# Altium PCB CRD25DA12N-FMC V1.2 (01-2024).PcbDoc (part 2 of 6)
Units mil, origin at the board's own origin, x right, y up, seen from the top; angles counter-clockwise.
Board outline 8000 x 8000 mil, 6 copper layers (Top Layer, Layer 2, Layer 3, Layer 4, Layer 5, Bottom Layer), stack 91 mil thick; 574 components, 325 nets, 1631 pads, 633 vias.
Unrouted connection lines stored in the file: 1.
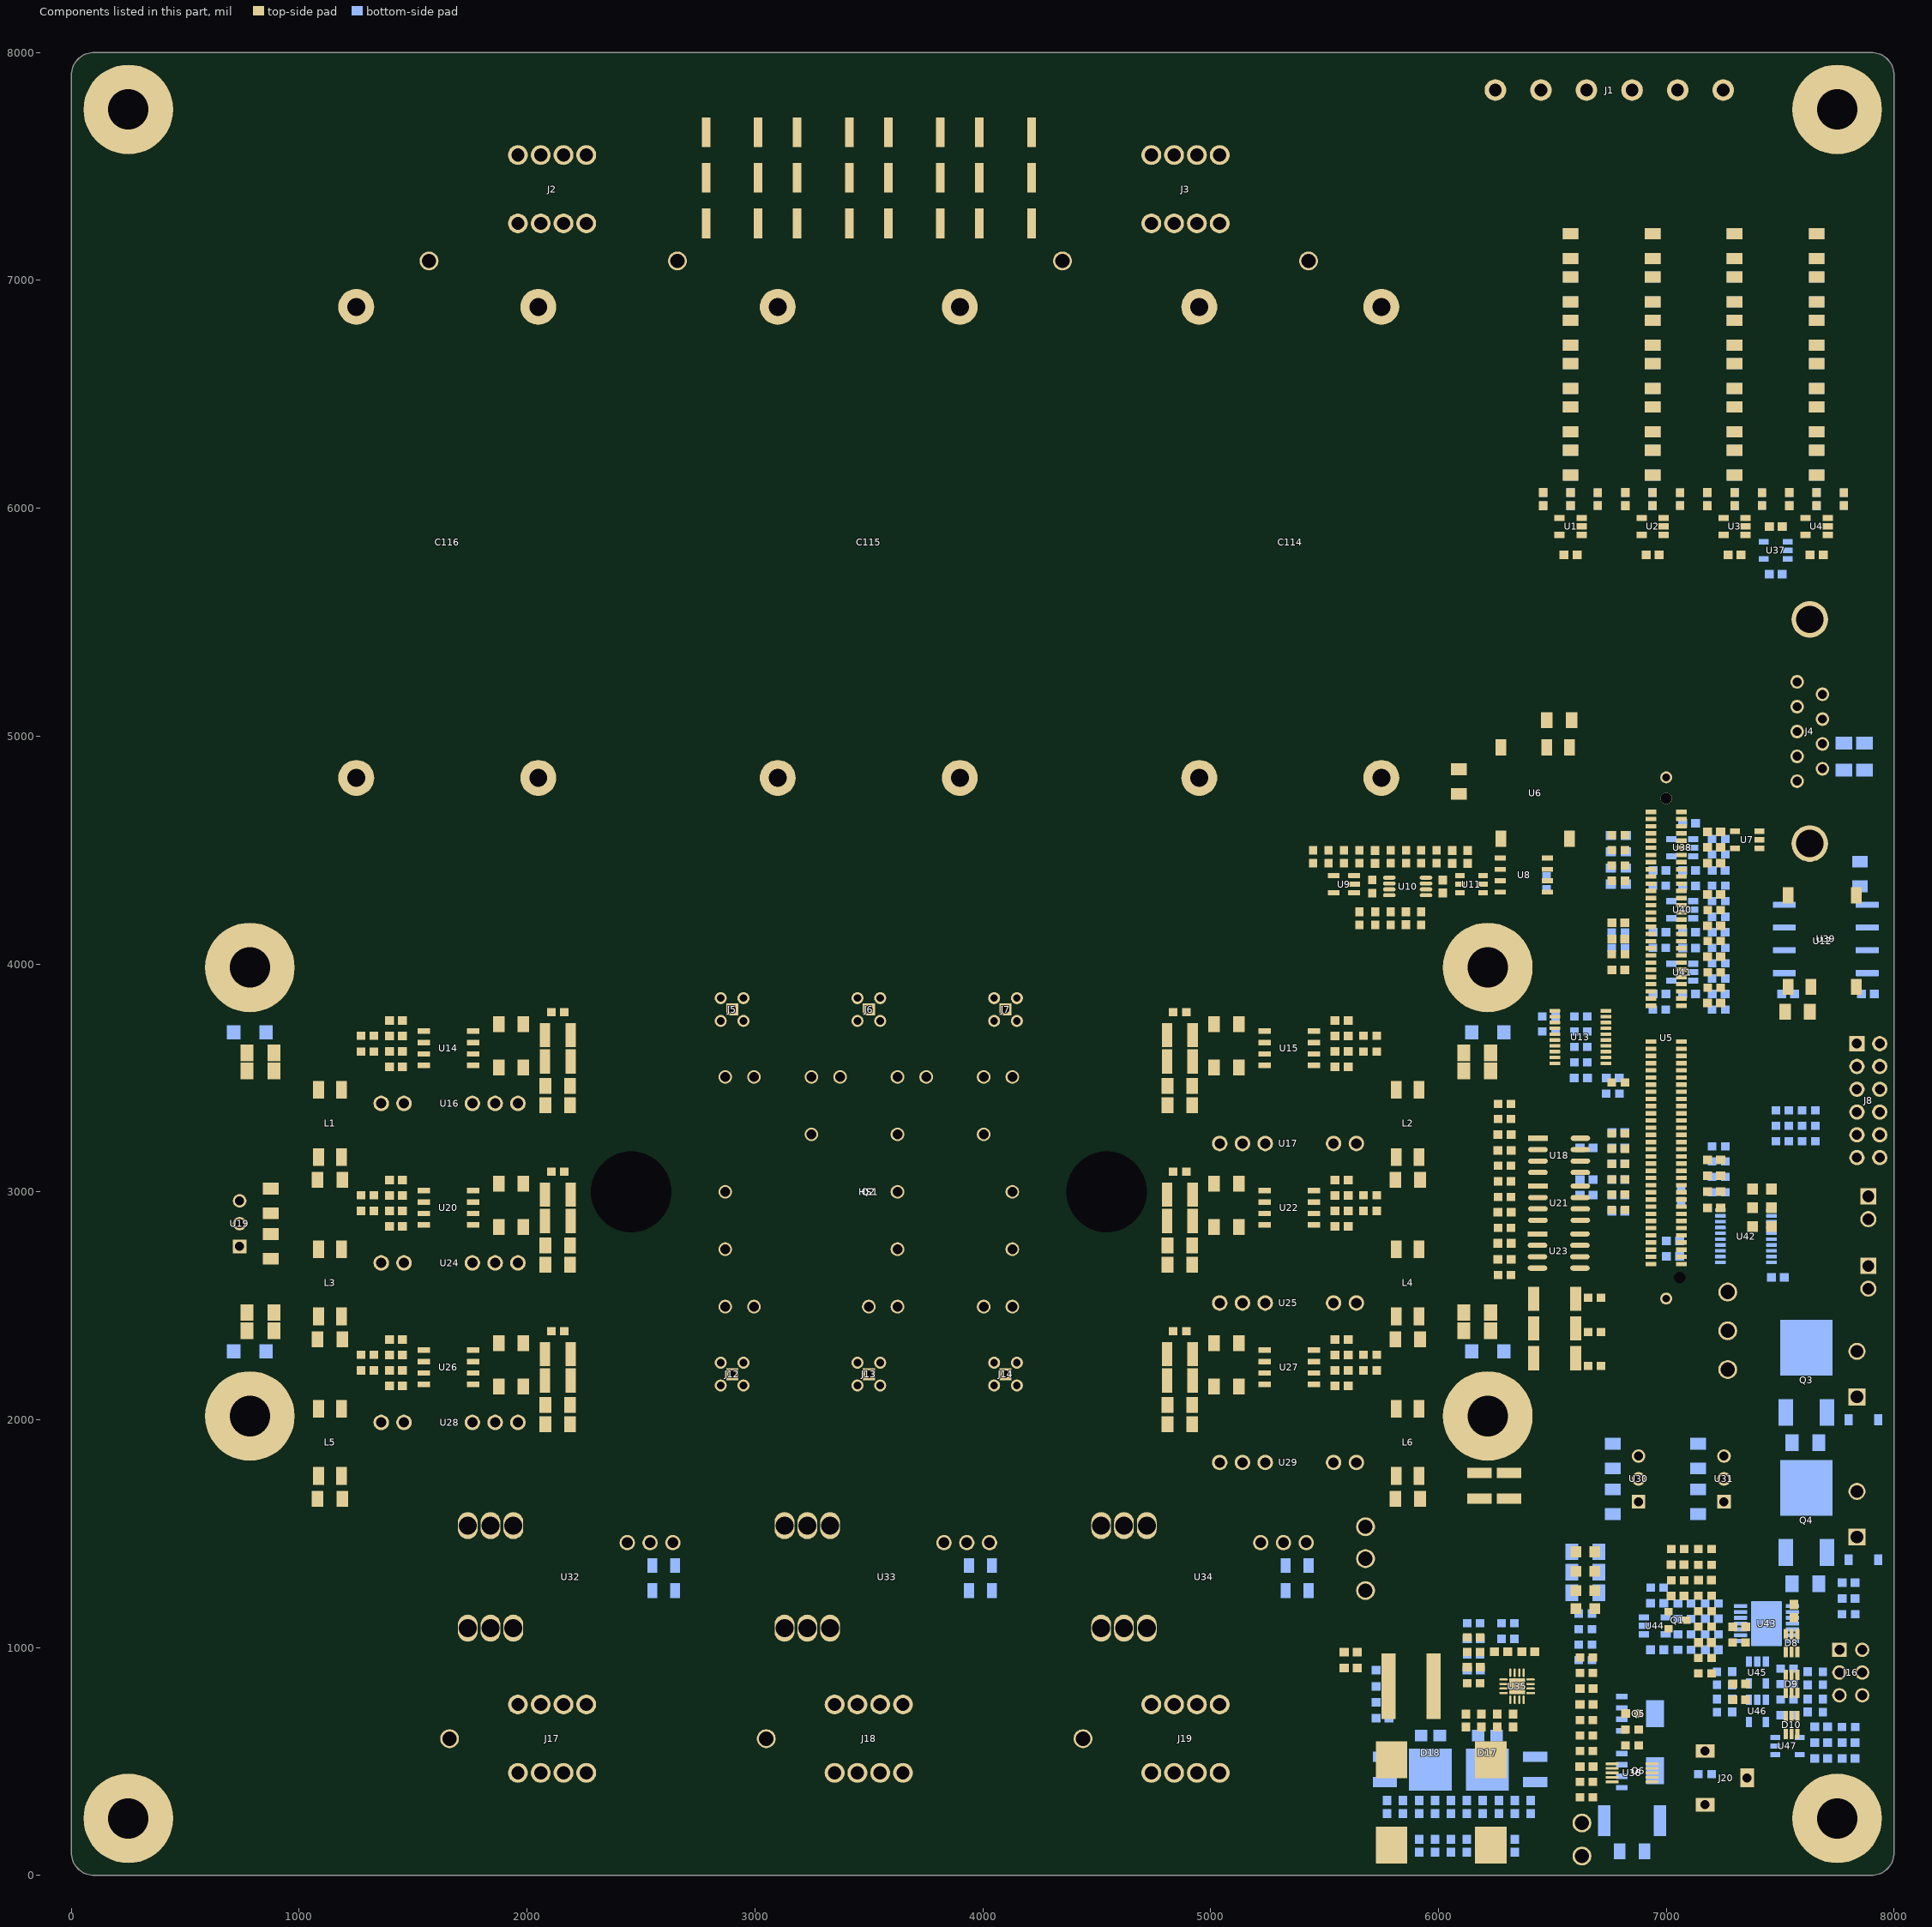
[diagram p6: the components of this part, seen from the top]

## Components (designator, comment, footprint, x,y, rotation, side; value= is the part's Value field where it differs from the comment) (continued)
R171 "TNPW1206249KBEEA" RESC3216X65X50NL15T25 6940,6200 r270 bottom value=249kΩ (schematic designator R178)
R172 "TNPW1206249KBEEA" RESC3216X65X50NL15T25 6580,6200 r270 bottom value=249kΩ (schematic designator R179)
R173 "ERJ-PB3B1801V" FP-MCR03-IPC_B 7780,6040 r90 bottom value=1.8kΩ (schematic designator R180)
R174 "RC0603FR-074K99L" FP-MCR03-IPC_B 7540,6040 r270 bottom value=4.99kΩ (schematic designator R181)
R175 "ERJ-PB3B1801V" FP-MCR03-IPC_B 7420,6040 r90 bottom value=1.8kΩ (schematic designator R182)
R176 "RC0603FR-074K99L" FP-MCR03-IPC_B 7180,6040 r270 bottom value=4.99kΩ (schematic designator R183)
R177 "ERJ-PB3B1801V" FP-MCR03-IPC_B 7060,6040 r90 bottom value=1.8kΩ (schematic designator R184)
R178 "RC0603FR-074K99L" FP-MCR03-IPC_B 6820,6040 r270 bottom value=4.99kΩ (schematic designator R185)
R179 "ERJ-PB3B3741V" FP-MCR03-IPC_B 6700,6040 r270 bottom value=3.74kΩ (schematic designator R186)
R180 "RC0603FR-074K99L" FP-MCR03-IPC_B 6460,6040 r270 bottom value=4.99kΩ (schematic designator R187)
R181 "RC1206FR-07249RL" FP-MCR18-IPC_A 7870,4910 r90 bottom value=249Ω (schematic designator R188)
R182 "RC1206FR-07249RL" FP-MCR18-IPC_A 7780,4910 r90 bottom value=249Ω (schematic designator R189)
R183 "RMCF0603FT1K33" FP-MCR03-IPC_B 7230,4548 r180 bottom value=1.33kΩ (schematic designator R190)
R184 "RMCF0603FT7K15" FP-MCR03-IPC_B 7230,4480 r180 bottom value=7.15kΩ (schematic designator R191)
R185 "ERA3AEB4021V" FP-MCR03-IPC_B 7230,4343 r0 bottom value=4.02kΩ (schematic designator R192)
R186 "RC0603FR-077K87L" FP-MCR03-IPC_B 6970,4343 r0 bottom value=7.87kΩ (schematic designator R193)
R187 "RMCF0603FT1K33" FP-MCR03-IPC_B 7230,4275 r180 bottom value=1.33kΩ (schematic designator R194)
R188 "RMCF0603FT7K15" FP-MCR03-IPC_B 7230,4207 r180 bottom value=7.15kΩ (schematic designator R195)
R189 "ERJ-3EKF49R9V" FP-MCR03-IPC_B 6790,4139 r0 bottom value=49.9Ω (schematic designator R196)
R190 "ERA3AEB4021V" FP-MCR03-IPC_B 7230,4070 r0 bottom value=4.02kΩ (schematic designator R197)
R191 "RC0603FR-077K87L" FP-MCR03-IPC_B 6970,4070 r0 bottom value=7.87kΩ (schematic designator R198)
R192 "ERJ-3EKF49R9V" FP-MCR03-IPC_B 6790,4070 r0 bottom value=49.9Ω (schematic designator R199)
R193 "RMCF0603FT1K33" FP-MCR03-IPC_B 7230,4003 r180 bottom value=1.33kΩ (schematic designator R200)
R194 "RMCF0603FT7K15" FP-MCR03-IPC_B 7230,3936 r180 bottom value=7.15kΩ (schematic designator R201)
R195 "ERA3AEB4021V" FP-MCR03-IPC_B 7230,3800 r0 bottom value=4.02kΩ (schematic designator R202)
R196 "RC0603FR-077K87L" FP-MCR03-IPC_B 6970,3800 r0 bottom value=7.87kΩ (schematic designator R203)
R197 "RC0603FR-07100KL" FP-MCR03-IPC_B 6625,3770 r180 bottom value=100kΩ (schematic designator R204)
R198 "RC0603FR-07100KL" FP-MCR03-IPC_B 6485,3770 r180 bottom value=100kΩ (schematic designator R205)
R199 "RC0603FR-07100KL" FP-MCR03-IPC_B 6625,3703 r180 bottom value=100kΩ (schematic designator R206)
R200 "RC0603FR-07100KL" FP-MCR03-IPC_B 6485,3703 r180 bottom value=100kΩ (schematic designator R207)
R201 "RC0603FR-07100KL" FP-MCR03-IPC_B 6625,3636 r180 bottom value=100kΩ (schematic designator R208)
R202 "RC0603FR-07100KL" FP-MCR03-IPC_B 6625,3568 r180 bottom value=100kΩ (schematic designator R209)
R203 "ERJ3EKF1002V" FP-MCR03-IPC_B 6765,3430 r180 bottom value=10kΩ (schematic designator R210)
R204 "RC0603FR-13330RL" FP-MCR03-IPC_B 7625,3358 r180 bottom value=330Ω (schematic designator R211)
R205 "RC0603FR-13330RL" FP-MCR03-IPC_B 7510,3358 r180 bottom value=330Ω (schematic designator R212)
R206 "RC0603FR-13330RL" FP-MCR03-IPC_B 7625,3290 r180 bottom value=330Ω (schematic designator R213)
R207 "RC0603FR-13330RL" FP-MCR03-IPC_B 7510,3290 r180 bottom value=330Ω (schematic designator R214)
R208 "RC0603FR-13330RL" FP-MCR03-IPC_B 7625,3222 r180 bottom value=330Ω (schematic designator R215)
R209 "RC0603FR-13330RL" FP-MCR03-IPC_B 7510,3222 r180 bottom value=330Ω (schematic designator R216)
R210 "CRCW06030000Z0EB" FP-MCR03-IPC_B 7230,3200 r180 bottom value=0Ω (schematic designator R217)
R211 "CRCW06030000Z0EB" FP-MCR03-IPC_B 7230,3133 r180 bottom value=0Ω (schematic designator R218)
R212 "CRCW06030000Z0EB" FP-MCR03-IPC_B 7230,3066 r180 bottom value=0Ω (schematic designator R219)
R213 "CRCW06030000Z0EB" FP-MCR03-IPC_B 7230,2998 r180 bottom value=0Ω (schematic designator R220)
R214 "RC1206FR-07249RL" FP-MCR18-IPC_A 7610.9,1899.76 r0 bottom value=249Ω (schematic designator R221)
R215 "RC1206FR-07249RL" FP-MCR18-IPC_A 6645,1420 r0 bottom value=249Ω (schematic designator R223)
R216 "RC1206FR-07249RL" FP-MCR18-IPC_A 6645,1330 r180 bottom value=249Ω (schematic designator R224)
R217 "RC1206FR-07249RL" FP-MCR18-IPC_A 7610.9,1280 r0 bottom value=249Ω (schematic designator R225)
R218 "ERJ3EKF3901V" FP-MCR03-IPC_B 6960,1263 r0 bottom value=3.9kΩ (schematic designator R226)
R219 "RC1206FR-07249RL" FP-MCR18-IPC_A 6645,1240 r0 bottom value=249Ω (schematic designator R227)
R220 "RC0603FR-07470KL" FP-MCR03-IPC_B 7200,1194 r180 bottom value=470kΩ (schematic designator R228)
R221 "ERA-3AED153V" FP-MCR03-IPC_B 7080,1194 r0 bottom value=15kΩ (schematic designator R229)
R222 "ERJ3EKF1002V" FP-MCR03-IPC_B 7800,1146 r180 bottom value=10kΩ (schematic designator R231)
R223 "CRCW06034K70FKTA" FP-MCR03-IPC_B 6645,1149 r180 bottom value=4.7kΩ (schematic designator R230)
R224 "ERJ3EKF3901V" FP-MCR03-IPC_B 7080,1126 r180 bottom value=3.9kΩ (schematic designator R232)
R225 "RT0603DRE0734K8L" FP-MCR03-IPC_B 6305,1038 r180 bottom value=34.8kΩ (schematic designator R253)
R226 "RT0603DRE072KL" FP-MCR03-IPC_B 6155,1106 r180 bottom value=2kΩ (schematic designator R261)
R227 "CRCW06034K70FKTA" FP-MCR03-IPC_B 6645,1081 r180 bottom value=4.7kΩ (schematic designator R233)
R228 "ERA-3AED153V" FP-MCR03-IPC_B 7200,1058 r180 bottom value=15kΩ (schematic designator R234)
R229 "ERJ3EKF1002V" FP-MCR03-IPC_B 7080,1058 r0 bottom value=10kΩ (schematic designator R235)
R230 "RT0603DRE0722K6L" FP-MCR03-IPC_B 6305,1106 r0 bottom value=22.6kΩ (schematic designator R258)
R231 "CRCW06034K70FKTA" FP-MCR03-IPC_B 6645,1013 r0 bottom value=4.7kΩ (schematic designator R236)
R232 "ERJ3EKF1002V" FP-MCR03-IPC_B 7080,990 r180 bottom value=10kΩ (schematic designator R237)
R233 "RT0603BRD075K36L" FP-MCR03-IPC_B 6155,970 r0 bottom value=5.36kΩ (schematic designator R252)
R234 "CRCW06034K70FKTA" FP-MCR03-IPC_B 6645,945 r0 bottom value=4.7kΩ (schematic designator R238)
R235 "ERJ-PB3B1212V" FP-MCR03-IPC_B 7530,907 r180 bottom value=12.1kΩ (schematic designator R239)
R236 "RC0603FR-0747KL" FP-MCR03-IPC_B 7688,865 r270 bottom value=47kΩ (schematic designator R240)
R237 "ERJ3EKF1002V" FP-MCR03-IPC_B 7222,865 r270 bottom value=10kΩ (schematic designator R241)
R238 "ERJ-PB3B1212V" FP-MCR03-IPC_B 7530,839 r180 bottom value=12.1kΩ (schematic designator R242)
R239 "RC0603FR-0747KL" FP-MCR03-IPC_B 7688,745 r90 bottom value=47kΩ (schematic designator R244)
R240 "ERJ-PB3B1212V" FP-MCR03-IPC_B 7530,771 r180 bottom value=12.1kΩ (schematic designator R243)
R241 "ERJ3EKF1002V" FP-MCR03-IPC_B 7222,745 r270 bottom value=10kΩ (schematic designator R245)
R242 "ERJ-PB3B1212V" FP-MCR03-IPC_B 7530,703 r180 bottom value=12.1kΩ (schematic designator R246)
R243 "ERJ3EKF1002V" FP-MCR03-IPC_B 7800,652 r0 bottom value=10kΩ (schematic designator R247)
R244 "CRCW121010R0FKEAHP" RESC3125X70X40NL20T20 6425,465 r270 bottom value=10Ω (schematic designator R251)
R245 "CRCW121010R0FKEAHP" RESC3125X70X40NL20T20 5765,465 r270 bottom value=10Ω (schematic designator R257)
R246 "RC0603FR-07100KL" FP-MCR03-IPC_B 7170,445 r0 bottom value=100kΩ (schematic designator R152)
R247 "PE2512FKE7W0R01L" FP-RL2512-IPC_A 6850,240 r180 bottom value=10mΩ (schematic designator R248)
TP1 "5010" KSTN-5010_V 1570,7085 r0 top value=RED
TP2 "5010" KSTN-5010_V 2660,7085 r0 top value=RED
TP3 "5011" KSTN-5011_V 4350,7085 r0 top value=BLACK
TP4 "5011" KSTN-5011_V 5430,7085 r0 top value=BLACK
TP5 "5010" KSTN-5010_V 7270,2560 r0 top value=RED
TP6 "5010" KSTN-5010_V 7270,2390 r0 top value=RED
TP7 "5011" KSTN-5011_V 7270,2220 r0 top value=BLACK
TP8 "5010" KSTN-5010_V 5680,1530 r0 top value=RED
TP9 "5010" KSTN-5010_V 5680,1390 r0 top value=RED
TP10 "5011" KSTN-5011_V 5680,1250 r0 top value=BLACK (schematic designator TP13)
TP11 "5012" KSTN-5012_V 1660,600 r0 top value=WHITE (schematic designator TP10)
TP12 "5012" KSTN-5012_V 3050,600 r0 top value=WHITE (schematic designator TP11)
TP13 "5012" KSTN-5012_V 4440,600 r0 top value=WHITE (schematic designator TP12)
TP14 "5010" KSTN-5010_V 6630,230 r0 top value=RED
TP15 "5011" KSTN-5011_V 6630,85 r0 top value=BLACK
U1 "AD8615AUJZ-REEL7" ADI-UJ-5_M 6580,5920 r180 top value=N/A
U2 "AD8615AUJZ-REEL7" ADI-UJ-5_M 6940,5920 r180 top value=N/A
U3 "AD8615AUJZ-REEL7" ADI-UJ-5_M 7300,5920 r180 top value=N/A
U4 "AD8615AUJZ-REEL7" ADI-UJ-5_M 7660,5920 r180 top value=N/A
U5 "TMDSCNCD280039C" TMDSCNCD280039C 7000,3675 r90 top locked value=N/A
U6 "R1SE-3.305/H2-R" FP-R1SE-0505-R-MFG 6425,4750 r270 top value=N/A
U7 "REF2033QDDCRQ1" FP-DDC0005A-MFG 7355,4545 r180 top value=N/A
U8 "ISO722MDR" D0008B_L 6375,4390 r0 top value=N/A
U9 "TS431IYLT" SOT95P280X145-5N 5585,4350 r180 top value=N/A (schematic designator U10)
U10 "MCP6292-E/MS" MSOP-MS8_L 5865,4340 r0 top value=N/A (schematic designator U9)
U11 "LTC6992CS6-2#TRMPBF" SOT95P280X100-6N 6145,4350 r0 top value=N/A
U12 "R1SE-3.305/H2-R" FP-R1SE-0505-R-MFG 7685,4100 r90 top value=N/A
U13 "SN74LV541ATPWR" PW0020A_L 6622.8,3678.98 r180 top value=N/A
U14 "UCC5350SBD" D0008B_HV 1655,3630 r0 top value=N/A
U15 "UCC5350SBD" D0008B_HV 5345,3630 r180 top value=N/A
U16 "MGJ2D121503SC" MGJ2D121509SC 1660,3300 r0 top value=N/A
U17 "MGJ2D121503SC" MGJ2D121509SC 5340,3300 r180 top value=N/A
U18 "TLV3502AID" FP-D0008A-IPC_B 6530,3160 r0 top value=N/A
U19 "R-78E5.0-1.0" CONV_R-78E5.0-1.0 650,2860 r90 top value=N/A
U20 "UCC5350SBD" D0008B_HV 1655,2930 r0 top value=N/A
U21 "TLV3502AID" FP-D0008A-IPC_B 6530,2950 r0 top value=N/A
U22 "UCC5350SBD" D0008B_HV 5345,2930 r180 top value=N/A
U23 "TLV3502AID" FP-D0008A-IPC_B 6528.06,2740 r0 top value=N/A
U24 "MGJ2D121503SC" MGJ2D121509SC 1660,2600 r0 top value=N/A
U25 "MGJ2D121503SC" MGJ2D121509SC 5340,2600 r180 top value=N/A
U26 "UCC5350SBD" D0008B_HV 1655,2230 r0 top value=N/A
U27 "UCC5350SBD" D0008B_HV 5345,2230 r180 top value=N/A
U28 "MGJ2D121503SC" MGJ2D121509SC 1660,1900 r0 top value=N/A
U29 "MGJ2D121503SC" MGJ2D121509SC 5340,1900 r180 top value=N/A
U30 "R-78E3.3-1.0" CONV_R-78E3.3-1.0 6790,1740 r90 top value=N/A
U31 "R-78E5.0-1.0" CONV_R-78E5.0-1.0 7165,1740 r90 top value=N/A
U32 "LAH 50-P" "LAH 50-P" 2110,1300 r90 top locked value=N/A
U33 "LAH 50-P" "LAH 50-P" 3500,1300 r90 top locked value=N/A
U34 "LAH 50-P" "LAH 50-P" 4890,1300 r90 top locked value=N/A
U35 "LM5157QRTERQ1" FP-RTE0016K-IPC_A 6345,830 r180 top value=N/A (schematic designator U49)
U36 "LTC4368IMS-2#PBF" SOP50P490X110-10N 6850,450 r0 top value=N/A
U37 "REF2033QDDCRQ1" FP-DDC0005A-MFG 7480,5815 r180 bottom value=N/A (schematic designator U38)
U38 "AD8615AUJZ-REEL7" ADI-UJ-5_M 7070,4510 r180 bottom value=N/A (schematic designator U39)
U39 "ISO1050DUBR" DUB0008A_M 7700,4110 r0 bottom value=N/A (schematic designator U41)
U40 "AD8615AUJZ-REEL7" ADI-UJ-5_M 7070,4238 r180 bottom value=N/A
U41 "AD8615AUJZ-REEL7" ADI-UJ-5_M 7070,3964 r180 bottom value=N/A (schematic designator U42)
U42 "SN74LV541ATPWR" PW0020A_L 7350,2805 r0 bottom value=N/A (schematic designator U43)
U43 "ALM2402FQPWPRQ1" FP-PWP0014H-MFG 7440,1105 r0 bottom value=N/A (schematic designator U44)
U44 "AD8615AUJZ-REEL7" ADI-UJ-5_M 6950,1095 r0 bottom value=N/A (schematic designator U45)
U45 "AD8615AUJZ-REEL7" ADI-UJ-5_M 7400,890 r270 bottom value=N/A (schematic designator U46)
U46 "AD8615AUJZ-REEL7" ADI-UJ-5_M 7400,721.77 r270 bottom value=N/A (schematic designator U47)
U47 "REF2033QDDCRQ1" FP-DDC0005A-MFG 7531.85,567.6 r0 bottom value=N/A (schematic designator U48)

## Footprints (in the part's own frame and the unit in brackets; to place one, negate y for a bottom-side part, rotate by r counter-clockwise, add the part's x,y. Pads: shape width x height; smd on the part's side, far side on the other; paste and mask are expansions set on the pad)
1755736 [mm] "THD, 2-Leads, Body 12.16x8.6mm, Pitch 5.08mm"
  rect 1.9x1.9 hole 1.4: 1(-2.54,0)
  round 1.9 hole 1.4: 2(2.54,0)
  silkscreen extent -6.08,-3.81 6.08,4.79, body extent -6.08,-3.8 6.16,4.87, height 12
1755778 [mm] "TERM BLOCK HDR 6POS VERT 5.08MM"
  round 2.4 hole 1.4: 1(-12.7,0) 2(-7.62,0) 3(-2.54,0) 4(2.54,0) 5(7.62,0) 6(12.7,0)
  silkscreen extent -16.24,-3.83 16.24,3.84, body extent -16.24,-3.84 16.24,4.76, height 12
7460307 [mm] "8 Pin Screw Terminal, Power Tap M4 Through Hole"
  round 2.21 hole 1.475: 1(-3.81,3.81) 2(-1.27,3.81) 3(1.27,3.81) 4(3.81,3.81) 5(3.81,-3.81) 6(1.27,-3.81) 7(-1.27,-3.81) 8(-3.81,-3.81)
  Top Layer keep-out region: -8.5,-8.5 8.5,-8.5 8.5,8.5 -8.5,8.5
  Bottom Layer keep-out region: -8.5,-8.5 8.5,-8.5 8.5,8.5 -8.5,8.5
  silkscreen extent -5.2,-5.2 5.2,5.2, body extent -4.5,-4.5 4.5,4.5, height 7
61200621621 [mm] "6 pins, straight, gold plating"
  rect 1.6x1.6 hole 1.1: 1(-2.54,-1.27)
  round 1.6 hole 1.1: 2(-2.54,1.27) 3(0,-1.27) 4(0,1.27) 5(2.54,-1.27) 6(2.54,1.27)
  silkscreen extent -7.74,-4.5 7.74,4.5, body extent -7.64,-4.43 7.64,4.75, height 9.13
74437368220 [mm]
  rect 4.1x3.5 smd: 1(-4.75,0) 2(4.75,0)
  Top Layer keep-out region: -2.7,-5 2.7,-5 2.7,5 -2.7,5
  silkscreen extent -5.5,-5.5 5.5,5.5, body extent -5.5,-5 5.5,5, height 3.7
ADI-UJ-5_M [mm] "SOT23, 5-Leads, Body 2.9x1.6mm, Pitch 0.95mm, IPC Low Density"
  rect 1.15x0.7 smd: 1(-1.225,0.95) 2(-1.225,0) 3(-1.225,-0.95) 4(1.225,-0.95) 5(1.225,0.95)
  silkscreen extent -1.35,-1.45 0.25,1.97, body extent -0.8,-1.45 0.8,1.45, height 1
C4AQQEW5650A3BJ [mm] "CAP FILM 65UF 5% 1.1KVDC RAD"
  round 4 hole 2: 1(-26.25,10.15) 2(-26.25,-10.15) 3(26.25,10.15) 4(26.25,-10.15)
  silkscreen extent -28.75,-22.5 28.75,22.5, body extent -29,-22.71 29.3,22.8, height 65.4
CONV_R-78E3.3-1.0 [mm]
  rect 1.508x1.508 hole 1: 1(-2.54,-2.25)
  round 1.508 hole 1: 2(0,-2.25) 3(2.54,-2.25)
  silkscreen extent -6.5,-4.25 5.75,4.25, body extent -5.8,-4.25 5.8,4.25, height 9.9
CONV_R-78E5.0-1.0 [mm]
  rect 1.508x1.508 hole 1: 1(-2.54,-2.25)
  round 1.508 hole 1: 2(0,-2.25) 3(2.54,-2.25)
  silkscreen extent -6.5,-4.25 5.75,4.25, body extent -5.8,-4.25 5.8,4.25, height 9.9
CUI-PJ-102B_V [mm] "THD, 3-Leads, Body 14.4x9mm, Height 11mm"
  rect 1.5x2.1 hole 1 slot 1.6 at 90 deg: 1(-3,0) 2(3,0)
  rect 2.1x1.5 hole 1 slot 1.6 at 0 deg: 3(0,4.7)
  silkscreen extent -4.42,-4.5 10.7,4.9, body extent -3.7,-4.5 10.7,4.9, height 11
D0008B_HV [mm]
  rect 1.4x0.6 smd paste+0 mask+0: 1(-2.75,1.905) 2(-2.75,0.635) 3(-2.75,-0.635) 4(-2.75,-1.905) 5(2.75,-1.905) 6(2.75,-0.635) 7(2.75,0.635) 8(2.75,1.905)
  silkscreen extent -3.3,-2.5 0.9,3.35, body extent -3.01,-2.45 3.01,2.45, height 1.63
D0008B_L [mm] "SOIC, 8-Leads, Body 5x4mm, Pitch 1.27mm, IPC High Density"
  rrect18% 1.25x0.55 smd: 1(-2.625,1.905) 2(-2.625,0.635) 3(-2.625,-0.635) 4(-2.625,-1.905) 5(2.625,-1.905) 6(2.625,-0.635) 7(2.625,0.635) 8(2.625,1.905)
  silkscreen extent -1.6,-2.5 1.6,2.5, body extent -3,-2.45 3,2.45, height 1.63
DUB0008A_M [mm] "SOP, 8-Leads, Body 6.7x9.6mm, Pitch 2.54mm, IPC Low Density"
  rrect14% 2.55x0.7 smd: 1(-4.625,3.81) 2(-4.625,1.27) 3(-4.625,-1.27) 4(-4.625,-3.81) 5(4.625,-3.81) 6(4.625,-1.27) 7(4.625,1.27) 8(4.625,3.81)
  silkscreen extent -4.75,-4.8 2.95,4.83, body extent -5.24,-4.75 5.24,4.75, height 4.85
FM3_SIX-PACK_3PHASE_CRW [mm]
  round 1.524 hole 1.1: DC+_1(-6.4,-6.4) DC+_2(3.2,-6.4) DC+_3(12.8,-6.4) DC-1(-16,0) DC-2(3.2,0) DC-3(16,0) G1(-12.8,-12.8) G2(-16,12.8) G3(-3.2,-12.8) G4(3.2,12.8) G5(6.4,-12.8) G6(16,12.8) NTC1(12.8,-12.8) NTC2(16,-12.8) S1(-16,-12.8) S2(-12.8,12.8) S3(-6.4,-12.8) S4(0,12.8) S5(3.2,-12.8) S6(12.8,12.8) U(-16,6.4) V(3.2,6.4) W(16,6.4)
  round 0 hole 9 unplated: MH1(-26.5,0) MH2(26.5,0)
  Bottom Layer keep-out circle w6.2: c16,12.8 r2
  Bottom Layer keep-out circle w6.2: c-16,12.8 r2
  Bottom Layer keep-out circle w6.2: c-12.8,12.8 r2
  Bottom Layer keep-out circle w6.2: c0,12.8 r2
  Bottom Layer keep-out circle w6.2: c12.8,12.8 r2
  Bottom Layer keep-out circle w6.2: c3.2,12.8 r2
  Bottom Layer keep-out circle w6.2: c16,-12.8 r2
  Bottom Layer keep-out circle w6.2: c12.8,-12.8 r2
  Bottom Layer keep-out circle w6.2: c6.4,-12.8 r2
  Bottom Layer keep-out circle w6.2: c3.2,-12.8 r2
  Bottom Layer keep-out circle w6.2: c-3.2,-12.8 r2
  Bottom Layer keep-out circle w6.2: c-6.4,-12.8 r2
  Bottom Layer keep-out circle w6.2: c-12.8,-12.8 r2
  Bottom Layer keep-out circle w6.2: c-16,-12.8 r2
  Bottom Layer keep-out circle w6.2: c-16,6.4 r2
  Bottom Layer keep-out circle w6.2: c-16,0 r2
  Bottom Layer keep-out circle w6.2: c-6.4,-6.4 r2
  Bottom Layer keep-out circle w6.2: c3.2,-6.4 r2
  Bottom Layer keep-out circle w6.2: c12.8,-6.4 r2
  Bottom Layer keep-out circle w6.2: c16,0 r2
  Bottom Layer keep-out circle w6.2: c16,6.4 r2
  Bottom Layer keep-out circle w6.2: c3.2,6.4 r2
  Bottom Layer keep-out circle w6.2: c3.2,0 r2
  silkscreen extent -31.52,-16.88 31.52,16.88, body extent -31.4,-16.9 31.4,16.9, height 11.98
FP-73415-1471-MFG [mm]
  rect 1.34x1.34 hole 0.84 paste-2539.97 mask+0: 1(0.01,0)
  round 1.34 hole 0.84 paste-2539.97 mask+0: 2(-1.27,1.27) 3(1.27,1.27) 4(-1.27,-1.27) 5(1.27,-1.27)
  silkscreen extent -2.54,-1.82 1.82,1.82, body extent -2.04,-2.04 2.04,2.04, height 0.25
FP-61301221121-MFG [mm]
  rect 1.7x1.7 hole 1.1 paste-2539.97 mask+0: 1(-6.35,-1.27)
  round 1.7 hole 1.1 paste-2539.97 mask+0: 2(-6.35,1.27) 3(-3.81,-1.27) 4(-3.81,1.27) 5(-1.27,-1.27) 6(-1.27,1.27) 7(1.27,-1.27) 8(1.27,1.27) 9(3.81,-1.27) 10(3.81,1.27) 11(6.35,-1.27) 12(6.35,1.27)
  silkscreen extent -8.38,-2.62 7.77,2.62, body extent -7.87,-2.72 7.87,2.72, height 0.25
FP-APTR3216SECK-MFG [mm]
  rect 1.5x1.6 smd paste+0 mask+0: 1(-1.8,0) 2(1.8,0)
  silkscreen extent -3.3,-1.4 1.9,1.4, body extent -1.6,-0.8 1.6,0.8, height 1.1
FP-C0603C-CF-IPC_B [mil]
  rect 39.63x37.73 smd paste+0 mask+0: 1(-28.58,0) 2(28.58,0)
  silkscreen extent -48,-35 48,35, body extent -31,-16 31,16, height 34
FP-CL31-IPC_B [mil]
  rect 51.4x69.22 smd paste+0 mask+0: 1(-54.19,0) 2(54.19,0)
  silkscreen extent -17,-35 17,35, body extent -63,-31 63,31, height 55
FP-CL31-IPC_C [mil]
  rect 43.52x65.28 smd paste+0 mask+0: 1(-50.25,0) 2(50.25,0)
  silkscreen extent -17,-34 17,34, body extent -63,-31 63,31, height 55
FP-CRGP2512-IPC_C [mil]
  rect 37.72x130.17 smd paste+0 mask+0: 1(-114.25,0) 2(114.25,0)
  silkscreen extent -84,-67 84,67, body extent -125,-63 125,63, height 26
FP-D0008A-IPC_B [mil]
  rect 85.4x22.92 smd paste+0 mask+0: 1(-93.06,75)
  rrect100% 85.4x22.92 smd paste+0 mask+0: 2(-93.06,25) 3(-93.06,-25) 4(-93.06,-75) 5(93.06,-75) 6(93.06,-25) 7(93.06,25) 8(93.06,75)
  silkscreen extent -162,-97 31,97, body extent -146,-106 146,106, height 10
FP-DDC0005A-MFG [mm]
  rect 1.1x0.6 smd paste+0 mask+0: 1(-1.35,0.95) 2(-1.35,0) 3(-1.35,-0.95) 4(1.35,-0.95) 5(1.35,0.95)
  silkscreen extent -2.6,-1.53 0.87,1.53, body extent -2,-1.63 2,1.63, height 0.25
FP-GCM188-0_1-IPC_A [mil]
  rect 45.62x39.85 smd paste+0 mask+0: 1(-32.55,0) 2(32.55,0)
  silkscreen extent -55,-36 55,36, body extent -31,-16 31,16, height 35
FP-LTST-C171GKT-MFG [mm]
  rect 1.2x1.2 smd paste+0 mask+0: 1(-1.05,0) 2(1.05,0)
  silkscreen extent -2.37,-1.05 1.05,1.05, body extent -1.75,-0.77 1.75,0.77, height 0.25
FP-LTST-C171GKT-MFG-RED [mm]
  rect 1.2x1.2 smd paste+0 mask+0: 1(-1.05,0) 2(1.05,0)
  silkscreen extent -2.37,-1.05 1.05,1.05, body extent -1,-0.63 1,0.63, height 0.8
FP-LTST-C171GKT-MFG-YELLOW [mm]
  rect 1.2x1.2 smd paste+0 mask+0: 1(-1.05,0) 2(1.05,0)
  silkscreen extent -2.37,-1.05 1.05,1.05, body extent -1,-0.63 1,0.63, height 0.8
FP-MCR03-IPC_B [mil]
  rect 37.72x35.91 smd paste+0 mask+0: 1(-28.62,0) 2(28.62,0)
  silkscreen extent -47,-34 47,34, body extent -31,-16 31,16, height 22
FP-MCR18-IPC_A [mil]
  rect 57.31x73.16 smd paste+0 mask+0: 1(-59.1,0) 2(59.1,0)
  silkscreen extent -19,-37 19,37, body extent -107,-56 107,56, height 10
FP-PowerDI5060-8-MFG [mm]
  rect 0.61x1.27 smd paste+0 mask+0: 1(-1.905,-2.67) 2(-0.635,-2.67) 3(0.635,-2.67) 4(1.905,-2.67)
  rect 3x2 smd paste+0 mask+0: 5(0,1.05)
  Top Layer region: 2.05,-1.215 -2.05,-1.215 -2.05,-1.035 -2.805,-1.035 -2.805,-0.435 -2.05,-0.435 -2.05,1.39 -2.805,1.39 -2.805,1.99 -2.05,1.99 -2.05,2.285 -2.21,2.285 -2.21,3.305 -1.6,3.305 -1.6,2.595 -0.94,2.595 -0.94,3.305 -0.33,3.305 -0.33,2.595 0.33,2.595 0.33,3.305 0.94,3.305 0.94,2.595 1.6,2.595 1.6,3.305 2.21,3.305 2.21,2.285 2.05,2.285 2.05,1.99 2.805,1.99 2.805,1.39 2.05,1.39 2.05,-0.435 2.805,-0.435 2.805,-1.035 2.05,-1.035
  silkscreen extent -3.2,-2.73 2.55,-1.59, body extent -2.58,-3.08 2.58,3.08, height 1.15
FP-PSMC_TO-277A-MFG [mm]
  rect 4.8x4.72 smd paste+0 mask+0: 1(0,1.04)
  rect 1.4x1.27 smd paste+0 mask+0: 2(-1.04,-2.765) 3(1.04,-2.765)
  silkscreen extent -2.22,-3.08 2.22,-1.7, body extent -2.3,-3.25 2.3,3.25, height 1.21
FP-PWP0014H-MFG [mm]
  rrect22% 1.5x0.45 smd paste+0 mask+0: 1(-2.9,1.95) 2(-2.9,1.3) 3(-2.9,0.65) 4(-2.9,0) 5(-2.9,-0.65) 6(-2.9,-1.3) 7(-2.9,-1.95) 8(2.9,-1.95) 9(2.9,-1.3) 10(2.9,-0.65) 11(2.9,0) 12(2.9,0.65) 13(2.9,1.3) 14(2.9,1.95)
  rrect3% 3.4x5 smd paste-1000 mask-1000: 15(0,0)
  silkscreen extent -4.35,-2.6 2.25,2.6, body extent -3.2,-2.5 3.2,2.5, height 1.2
FP-R1SE-0505-R-MFG [mm]
  rect 1.8x1.2 smd paste+0 mask+0: 1(-5.1,3.81) 2(-5.1,1.27) 4(-5.1,-3.81) 5(5.1,-3.81) 8(5.1,3.81)
  silkscreen extent -5.35,-6.5 5.35,6.5, body extent -6.1,-6.6 6.1,6.6, height 0.25
FP-RL2512-IPC_A [mil]
  rect 53.47x136.15 smd paste+0 mask+0: 1(-122.13,0) 2(122.13,0)
  silkscreen extent -84,-68 84,68, body extent -123,-63 127,63, height 26
FP-RTE0016K-IPC_A [mm]
  rect 0.949x0.239 smd paste+0 mask+0: 1(-1.505,0.75)
  rrect100% 0.949x0.239 smd paste+0 mask+0: 2(-1.505,0.25) 3(-1.505,-0.25) 4(-1.505,-0.75) 9(1.505,-0.75) 10(1.505,-0.25) 11(1.505,0.25) 12(1.505,0.75)
  rrect100% 0.239x0.949 smd paste+0 mask+0: 5(-0.75,-1.505) 6(-0.25,-1.505) 7(0.25,-1.505) 8(0.75,-1.505) 13(0.75,1.505) 14(0.25,1.505) 15(-0.25,1.505) 16(-0.75,1.505)
  rect 1.76x1.76 smd paste-1000 mask+0: 17(0,0)
  silkscreen extent -2.02,-1.5 1.5,1.5, body extent -2.48,-2.48 2.48,2.48, height 0.25
KSTN-5010_V [mm] "Test Point, Dia 3.17mm"
  round 2.1 hole 1.6: 1(0,0)
  silkscreen extent -1.59,-1.58 1.59,1.58, body extent -1.59,-1.59 1.59,1.59, height 8.13
KSTN-5011_V [mm] "Test Point, Dia 3.17mm"
  round 2.1 hole 1.6: 1(0,0)
  silkscreen extent -1.59,-1.58 1.59,1.58, body extent -1.59,-1.59 1.59,1.59, height 8.13
KSTN-5012_V [mm] "Test Point, Dia 3.17mm"
  round 2.1 hole 1.6: 1(0,0)
  silkscreen extent -1.59,-1.58 1.59,1.58, body extent -1.59,-1.59 1.59,1.59, height 8.13
L717SDE09PA4CH4RC309 [mm] "CONN D-SUB PLUG 9POS R/A SLDR"
  round 1.508 hole 1: 1(-5.54,1.42) 2(-2.77,1.42) 3(0,1.42) 4(2.77,1.42) 5(5.54,1.42) 6(-4.155,-1.42) 7(-1.385,-1.42) 8(1.385,-1.42) 9(4.155,-1.42)
  round 4.066 hole 3.05: 10(-12.495,0) 11(12.495,0)
  silkscreen extent -15.7,-8.5 15.7,3.4, body extent -15.4,-15.6 15.41,3, height 12.55
"LA 6 150 12" [mm]
  round 10 hole 4.5: 1(-69,25) 2(69,25) 3(-69,-25) 4(69,-25)
  body extent -104.53,-31.05 74.97,30.95, height 86.05
"LAH 50-P" [mil]
  oval 118.74x86.61 hole 78.74 mask+7.87: 1(235,370) 2(235,270) 3(235,170) 5(-215,270) 6(-215,170)
  oval 118.74x86.61 hole 78.74 paste-99999 mask+7.87: 4(-215,370)
  round 67.24 hole 47.24: 7(160,-330) 8(160,-430) 9(160,-530)
  silkscreen extent -285,-635 305,675, body extent -284,-636 304,675, height 790
MGJ2D121509SC [mm]
  round 1.725 hole 1.15: 1(-7.62,2.23) 2(-5.08,2.23) 5(2.54,2.23) 6(5.08,2.23) 7(7.62,2.23)
  silkscreen extent -10.52,-4.9 9.75,4.9, body extent -9.9,-5.09 9.6,4.73, height 13.09
MH_M4_P [mm] "M4 plated mounting hole"
  round 10 hole 4.5: 1(0,0)
  body extent -4,-4.62 4,4.62
MSOP-MS8_L [mm] "TSOP, 8-Leads, Body 3x3mm, Pitch 0.65mm, IPC High Density"
  oval 1.4x0.45 smd: 1(-2.05,0.975) 2(-2.05,0.325) 3(-2.05,-0.325) 4(-2.05,-0.975) 5(2.05,-0.975) 6(2.05,-0.325) 7(2.05,0.325) 8(2.05,0.975)
  silkscreen extent -2.17,-1.55 0.95,1.87, body extent -1.55,-1.55 1.55,1.55, height 1.1
ONSC-DPAK-3-369C-01_V [mm] "DPAK, 3-Leads, Body 6.54x6.095mm, Pitch 2.29mm"
  rect 3x1.6 smd: 1(-4.4,2.29) 3(-4.4,-2.29)
  rect 6.2x5.8 smd: 4(2.8,0)
  silkscreen extent -4.52,-3.27 -0.45,3.77, body extent -1.6,-3.27 4.49,3.27, height 2.38
ONSC-SOD-123FL-2-498-01_V [mm] "SOD, 2-Leads, Body 2.7x1.65mm"
  rect 0.91x1.22 smd: 1(-1.635,0) 2(1.635,0)
  silkscreen extent -0.78,-0.82 0.78,0.82, body extent -1.35,-0.82 1.35,0.82, height 1
ONSC-SOT-23-3-318-08_V [mm] "SOT23, 3-Leads, Body 2.92x1.3mm, Pitch 0.95mm"
  rect 0.9x0.8 smd: 1(-1,0.95) 2(-1,-0.95) 3(1,0)
  silkscreen extent -1.12,-1.46 0.65,2.02, body extent -0.65,-1.46 0.65,1.46, height 1.11
PW0020A_L [mm] "SOP, 20-Leads, Body 6.6x4.5mm, Pitch 0.65mm, IPC High Density"
  rrect25% 1.2x0.4 smd: 1(-2.85,2.925) 2(-2.85,2.275) 3(-2.85,1.625) 4(-2.85,0.975) 5(-2.85,0.325) 6(-2.85,-0.325) 7(-2.85,-0.975) 8(-2.85,-1.625) 9(-2.85,-2.275) 10(-2.85,-2.925) 11(2.85,-2.925) 12(2.85,-2.275) 13(2.85,-1.625) 14(2.85,-0.975) 15(2.85,-0.325) 16(2.85,0.325) 17(2.85,0.975) 18(2.85,1.625) 19(2.85,2.275) 20(2.85,2.925)
  silkscreen extent -2.98,-3.3 1.85,3.8, body extent -3.21,-3.25 3.21,3.25, height 1
RESC2010(5025)_N [mm] "Chip Resistor, Body 5.0x2.5mm, IPC Medium Density"
  rect 1.25x2.7 smd: 1(-2.35,0) 2(2.35,0)
  silkscreen extent -1.35,-1.25 1.35,1.25, body extent -2.6,-1.35 2.6,1.35, height 0.71
RESC3125X70X40NL20T20 [mm] "Chip Resistor, 2-Leads, Body 3.10x2.50mm, IPC Medium Density"
  rect 1.15x2.7 smd: 1(-1.425,0) 2(1.425,0)
  silkscreen extent -0.45,-1.25 0.45,1.25, body extent -1.65,-1.35 1.65,1.35, height 0.7
RESC3216X65X50NL15T25 [mm] "Chip Resistor, 2-Leads, Body 3.20x1.60mm, IPC Medium Density"
  rect 1.25x1.75 smd: 1(-1.4,0) 2(1.4,0)
  silkscreen extent -0.4,-0.77 0.4,0.77, body extent -1.68,-0.87 1.68,0.87, height 0.65
SOP50P490X110-10N [mm]
  rect 1.425x0.3 smd: 1(-2.212,1) 2(-2.212,0.5) 3(-2.212,0) 4(-2.212,-0.5) 5(-2.212,-1) 6(2.212,-1) 7(2.212,-0.5) 8(2.212,0) 9(2.212,0.5) 10(2.212,1)
  silkscreen extent -2.92,-1.5 1.15,1.5, body extent -2.45,-1.5 2.45,1.5, height 1.1
SOT65P222X120-6N [mm]
  rect 1.15x0.45 smd: 1(-1,0.65) 2(-1,0) 3(-1,-0.65) 4(1,-0.65) 5(1,0) 6(1,0.65)
  silkscreen extent -1.58,-1 0.08,1.22, body extent -1.11,-1 1.11,1, height 1.2
SOT95P280X100-6N [mm]
  rect 1.05x0.55 smd: 1(-1.3,0.95) 2(-1.3,0) 3(-1.3,-0.95) 4(1.3,-0.95) 5(1.3,0) 6(1.3,0.95)
  silkscreen extent -1.83,-1.45 0.43,1.58, body extent -1.4,-1.45 1.4,1.45, height 1
SOT95P280X145-5N [mm]
  rrect25% 1.32x0.59 smd: 1(-1.145,0.95) 2(-1.145,0) 3(-1.145,-0.95) 4(1.145,-0.95) 5(1.145,0.95)
  silkscreen extent -2.51,-1.57 0.8,1.57, body extent -1.25,-1.5 1.25,1.5, height 1.11
TECO-640456-2_V [mm] "HDR, 2-Leads, Body 5.715x5.08mm, Pitch 2.54mm"
  rect 1.8x1.8 hole 1.3: 1(1.27,0)
  round 1.8 hole 1.3: 2(-1.27,0)
  silkscreen extent -2.54,-2.54 3.26,3.17, body extent -2.54,-2.67 2.54,3.17, height 10.09
TMDSCNCD280039C [mm]
  rect 0.5x1.2 smd paste+0 mask+0: 1(25.2,1.7) 2(25.2,-1.7) 3(24.4,1.7) 4(24.4,-1.7) 5(23.6,1.7) 6(23.6,-1.7) 7(22.8,1.7) 8(22.8,-1.7) 9(22,1.7) 10(22,-1.7) 11(21.2,1.7) 12(21.2,-1.7) 13(20.4,1.7) 14(20.4,-1.7) 15(19.6,1.7) 16(19.6,-1.7) 17(18.8,1.7) 18(18.8,-1.7) 19(18,1.7) 20(18,-1.7) 21(17.2,1.7) 22(17.2,-1.7) 23(16.4,1.7) 24(16.4,-1.7) 25(15.6,1.7) 26(15.6,-1.7) 27(14.8,1.7) 28(14.8,-1.7) 29(14,1.7) 30(14,-1.7) 31(13.2,1.7) 32(13.2,-1.7) 33(12.4,1.7) 34(12.4,-1.7) 35(11.6,1.7) 36(11.6,-1.7) 37(10.8,1.7) 38(10.8,-1.7) 39(10,1.7) 40(10,-1.7) 41(9.2,1.7) 42(9.2,-1.7) 43(8.4,1.7) 44(8.4,-1.7) 45(7.6,1.7) 46(7.6,-1.7) 47(6.8,1.7) 48(6.8,-1.7) 49(6,1.7) 50(6,-1.7) 51(5.2,1.7) 52(5.2,-1.7) 53(4.4,1.7) 54(4.4,-1.7) 55(3.6,1.7) 56(3.6,-1.7) 57(-0.4,1.7) 58(-0.4,-1.7) 59(-1.2,1.7) 60(-1.2,-1.7) 61(-2,1.7) 62(-2,-1.7) 63(-2.8,1.7) 64(-2.8,-1.7) 65(-3.6,1.7) 66(-3.6,-1.7) 67(-4.4,1.7) 68(-4.4,-1.7) 69(-5.2,1.7) 70(-5.2,-1.7) 71(-6,1.7) 72(-6,-1.7) 73(-6.8,1.7) 74(-6.8,-1.7) 75(-7.6,1.7) 76(-7.6,-1.7) 77(-8.4,1.7) 78(-8.4,-1.7) 79(-9.2,1.7) 80(-9.2,-1.7) 81(-10,1.7) 82(-10,-1.7) 83(-10.8,1.7) 84(-10.8,-1.7) 85(-11.6,1.7) 86(-11.6,-1.7) 87(-12.4,1.7) 88(-12.4,-1.7) 89(-13.2,1.7) 90(-13.2,-1.7) 91(-14,1.7) 92(-14,-1.7) 93(-14.8,1.7) 94(-14.8,-1.7) 95(-15.6,1.7) 96(-15.6,-1.7) 97(-16.4,1.7) 98(-16.4,-1.7) 99(-17.2,1.7) 100(-17.2,-1.7) 101(-18,1.7) 102(-18,-1.7) 103(-18.8,1.7) 104(-18.8,-1.7) 105(-19.6,1.7) 106(-19.6,-1.7) 107(-20.4,1.7) 108(-20.4,-1.7) 109(-21.2,1.7) 110(-21.2,-1.7) 111(-22,1.7) 112(-22,-1.7) 113(-22.8,1.7) 114(-22.8,-1.7) 115(-23.6,1.7) 116(-23.6,-1.7) 117(-24.4,1.7) 118(-24.4,-1.7) 119(-25.2,1.7) 120(-25.2,-1.7)
  round 1.34 hole 0.84 paste-2539.97 mask+0: 121(-29.05,0) 122(29.05,0)
  round 0 hole 1.27 unplated paste-2539.97 mask+0: ""(-26.7,-1.5)
  round 1.27 hole 1.27 unplated paste-2539.97 mask+0: ""(26.7,0)
  silkscreen extent -33.55,-4.25 33.55,3.56, body extent -33.87,-4.89 34.67,5.68, height 57.35
WE-SL2 [mm] "SMD Inductor, 4-Leads, Body 6.3 x 9.5 mm"
  rect 2x1.2 smd: 1(-3.75,1.27) 2(-3.75,-1.27) 3(3.75,-1.27) 4(3.75,1.27)
  silkscreen extent -4.7,-3.18 4.7,3.18, body extent -4.6,-3 4.6,3, height 5
WE-XHMI_8080_L8.8W8.3H7.8 [mm] "SMT Power Inductor, 2-Leads, body 8.8x8.3mm"
  rect 7.35x1.6 smd: 1(0,2.5) 2(0,-2.5)
  Top Layer keep-out region: -4.4,1.5 4.4,1.5 4.4,-1.5 -4.4,-1.5
  silkscreen extent -4.5,-4.25 4.5,4.25, body extent -4.4,-4.15 4.4,4.15, height 7.8

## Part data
C1 C21 C23 C25 C45 C69 C70 C108 C120 C128 C134 C140 C170: "CAP CER 4700PF 25V 10% X7R 0603", Capacitance=4.7nF, Case Code (Imperial)=0603, Case Code (Metric)=1608, Dielectric=X7R, Dielectric Material=Ceramic, Manufacturer=KEMET, Manufacturer Part Number=C0603C472K3RACTU, Max Operating Temperature=125°C, Min Operating Temperature=-55°C, Package Quantity=1, Supplier Part Number 1=67AH9250, Tolerance=10%, Voltage Rating=25V
C2 C3 C4 C94 C98 C117 C118 C119: "CAP CER 10000PF 25V X7R 0603", Capacitance=10nF, Case Code (Imperial)=0603, Case Code (Metric)=1608, Manufacturer=SAMSUNG, Max Operating Temperature=125°C, Min Operating Temperature=-55°C, Ratings=AEC-Q200, Tolerance=10%, Voltage Rating=25V
C5 C6 C7 C8 C9 C12 C13 C14 C15 C16 C17 C18 C20 C44 C61 C93 C96 C104 C106 C121 C122 C123 C131 C133 C137 C138 C139 C147 C150 C151 C153 C155 C156 C165 C173 C174 C184 C186 C187 C188: library part CMP-2006-03057-2, "CAP CER 0.1UF 25V X7R 0603", Capacitance=0.10μF, Manufacturer=KEMET, Package=0603, Temperature="-55°C to +125°C", Temperature Characteristic=X7R, Temperature Coefficient=30ppm/°C, Temperature Range High=+125°C, Temperature Range Low=-55°C, Tolerance=0.1, Voltage Rating=25V
C10 C11 C27 C30 C31 C36 C37 C40 C41 C42 C43 C48 C49 C52 C53 C54 C62 C63 C66 C67 C68 C71 C72 C73 C74 C77 C78 C83 C84 C87 C88 C89 C90 C91 C92 C126 C158 C159 C160 C161 C207: library part CMP-13271-001434-1, "CAP CER 10UF 25V X7R 1206", Capacitance=10μF, Case Code (Imperial)=1206, Case Code (Metric)=3216, Dielectric=X7R, Manufacturer=SAMSUNG, Max Operating Temperature=125°C, Min Operating Temperature=-55°C, Package Quantity=1, Tolerance=10%, Voltage Rating=25V
C19 C22 C95 C102: library part CMP-2006-03716-2, "CAP CER 1000PF 50V X7R 0603", Capacitance=1nF, Manufacturer=KEMET, Package=0603, Temperature="-55°C to +125°C", Temperature Characteristic=X7R, Temperature Coefficient=30ppm/°C, Temperature Range High=+125°C, Temperature Range Low=-55°C, Tolerance=0.1, Voltage Rating="50 V"
C24 C26 C32 C33 C34 C35 C46 C47 C55 C56 C57 C58 C59 C60 C79 C80 C81 C82 C113 C143 C145 C146 C148 C149 C152 C154: "CAP CER 56PF 50V C0G/NP0 0603", Capacitance=56pF, Case Code (Imperial)=0603, Case Code (Metric)=1608, Dielectric=C0G, Manufacturer=SAMSUNG, Max Operating Temperature=125°C, Min Operating Temperature=-55°C, Package Quantity=1, Temperature Coefficient=30ppm/°C, Tolerance=5%, Voltage=50V
C28 C29 C38 C39 C50 C51 C64 C65 C75 C76 C85 C86 C144 C157: "CAP CER 2.2UF 50V X5R 0603", Capacitance=2.2μF, Case Code (Imperial)=0603, Case Code (Metric)=1608, Manufacturer=MURATA, Max Operating Temperature=85°C, Min Operating Temperature=-55°C, Ratings=AEC-Q200, Tolerance=20%, Voltage Rating=50V
C97 C171: "CAP CER 18PF 50V C0G/NP0 0603", Capacitance=18pF, Case Code (Imperial)=0603, Case Code (Metric)=1608, Dielectric=C0G, Dielectric Material=Ceramic, Insulation Resistance=100GR, Manufacturer="KYOCERA AVX", Max Operating Temperature=125°C, Min Operating Temperature=-55°C, Package Quantity=1, Supplier Part Number 1=1349617, Temperature Coefficient=30ppm/°C, Tolerance=5%, Voltage=50V
C99 C105: "CAP CER 10000PF 100V X7R 0603", Capacitance=10nF, Case Code (Imperial)=0603, Case Code (Metric)=1608, Dielectric=X7R, Manufacturer=MURATA, Max Operating Temperature=125°C, Min Operating Temperature=-55°C, Package Quantity=1, Ratings=AEC-Q200, Supplier Part Number 1=81-GCM188R72A103KA7D, Tolerance=10%, Voltage=100V
C100: "CAP CER 220PF 100V C0G/NP0 0603", Capacitance=220pF, Case Code (Imperial)=0603, Case Code (Metric)=1608, Dielectric=C0G, Manufacturer=MURATA, Max Operating Temperature=125°C, Min Operating Temperature=-55°C, Package Quantity=1, Ratings=AEC-Q200, Supplier Part Number 1=81-GCM1885C2A221J16D, Temperature Coefficient=30ppm/°C, Tolerance=5%, Voltage=100V
C101 C129 C130 C135 C136 C141 C142: "CAP CER 100PF 50V C0G/NP0 0603", Capacitance=100pF, Case Code (Imperial)=0603, Case Code (Metric)=1608, Dielectric=C0G, Manufacturer=SAMSUNG, Max Operating Temperature=125°C, Min Operating Temperature=-55°C, Package Quantity=1, Supplier Part Number 1=7665130, Temperature Coefficient=300ppm/°C, Tolerance=5%, Voltage=50V
C103: "CAP CER 0.068UF 50V X7R 0603", Capacitance=68nF, Case Code (Imperial)=0603, Case Code (Metric)=1608, Dielectric=X7R, Manufacturer=TDK, Max Operating Temperature=125°C, Min Operating Temperature=-55°C, Package Quantity=4000, Ratings=AEC-Q200, Supplier Part Number 1=445-5665-1-ND, Tolerance=10%, Voltage Rating=50V
C107 C192 C195: "CAP CER 1UF 35V X7R 0603", Capacitance=1μF, Case Code (Imperial)=0603, Case Code (Metric)=1608, Dielectric=X7R, Manufacturer=TDK, Max Operating Temperature=125°C, Min Operating Temperature=-55°C, Package Quantity=4000, Ratings=AEC-Q200, Supplier Part Number 1=68AH9307, Tolerance=10%, Voltage Rating=35V
C109 C110 C111 C112 C179 C182 C183 C190 C191 C196 C197 C199 C200 C201 C202 C203 C204 C205 C206: "CAP CER 10UF 35V X5R 0603", Capacitance=10μF, Case Code (Imperial)=0603, Case Code (Metric)=1608, Dielectric=X5R, Manufacturer=MURATA, Max Operating Temperature=85°C, Min Operating Temperature=-55°C, Supplier Part Number 1=81-GRM188R6YA106MA3D, Tolerance=20%, Voltage Rating=35V
C114 C115 C116: "CAP FILM 65UF 5% 1.1KVDC RAD", Capacitance=65µF, Manufacturer=KEMET, Package=RADIAL, Supplier Part Number 1=399-C4AQQEW5650A3BJ-ND, Voltage=1.1kV
C124 C125 C127 C132: library part CMP-06035-043171-1, "CAP CER 0.27UF 16V X7R 0603", Capacitance=0.27μF, Dielectric=X7R, Manufacturer=MURATA, Package=0603, Tolerance=10%, Voltage Rating (DC)=16V
C162 C163 C164 C166 C167 C168: library part CMP-13271-001123-1, "CAP CER 4.7UF 50V X7R 1206", Capacitance=4.7μF, Case Code (Imperial)=1206, Case Code (Metric)=3216, Dielectric=X7R, Manufacturer=SAMSUNG, Max Operating Temperature=125°C, Min Operating Temperature=-55°C, Package Quantity=1, Tolerance=10%, Voltage Rating=50V
C169 C178 C181 C185: library part CMP-03020-020944-2, "CAP CER 330PF 250V C0G/NP0 0603", Capacitance=330pF, Manufacturer=KEMET, Package=0603, Temperature="-55°C to +125°C", Temperature Characteristic=C0G, Temperature Coefficient=30ppm/°C, Temperature Range High=+125°C, Temperature Range Low=-55°C, Tolerance=0.05, Voltage Rating="250 V"
C172: "CAP CER 0.047UF 50V X7R 0603", Capacitance=47nF, Case Code (Imperial)=0603, Case Code (Metric)=1608, Dielectric=X7R, Manufacturer=TDK, Max Operating Temperature=125°C, Min Operating Temperature=-55°C, Package Quantity=1, Ratings=AEC-Q200, Supplier Part Number 1=80X3178, Tolerance=10%, Voltage Rating=50V
C175: "CAP CER 0.22UF 25V X7R 0603", Capacitance=220nF, Case Code (Imperial)=0603, Case Code (Metric)=1608, Dielectric=X7R, Manufacturer=MURATA, Max Operating Temperature=125°C, Min Operating Temperature=-55°C, Package Quantity=1, Ratings=AEC-Q200, Supplier Part Number 1=81-GCM188R71E224K55D, Tolerance=10%, Voltage=25V
C176 C193 C194: "CAP CER 0.1UF 50V X7R 0603", Capacitance=100nF, Case Code (Imperial)=0603, Case Code (Metric)=1608, Dielectric=X7R, Manufacturer=TDK, Max Operating Temperature=125°C, Min Operating Temperature=-55°C, Package Quantity=1, Ratings=AEC-Q200, Tolerance=10%, Voltage=50V
C177 C180: "CAP CER 47PF 100V C0G/NP0 0603", Capacitance=47pF, Case Code (Imperial)=0603, Case Code (Metric)=1608, Dielectric=C0G, Dielectric Material=Ceramic, Manufacturer=KEMET, Max Operating Temperature=125°C, Min Operating Temperature=-55°C, Package Quantity=4000, Supplier Part Number 1=8015369, Temperature Coefficient=30ppm/°C, Tolerance=5%, Voltage=100V
C189 C198: "CAP CER 680PF 50V C0G/NP0 0603", Capacitance=680pF, Case Code (Imperial)=0603, Case Code (Metric)=1608, Dielectric=C0G, Dielectric Material=Ceramic, Manufacturer=KEMET, Max Operating Temperature=125°C, Min Operating Temperature=-55°C, Package Quantity=4000, Supplier Part Number 1=80-C0603C681J5G, Temperature Coefficient=30ppm/°C, Tolerance=5%, Voltage=50V
D1: "LED RED DIFFUSED 0805 SMD", Case Code (Imperial)=0805, Case Code (Metric)=2012, Color=RED, Forward Current=20mA, Forward Voltage=2V, Illumination Color=Red, Manufacturer="VISUAL COMMUNICATIONS", Max Operating Temperature=85°C, Min Operating Temperature=-40°C, Package Quantity=1, Power Rating=100mW, Reverse Voltage=5V, Supplier Part Number 1=45X6246
D2: "LED YELLOW CLEAR 0805 SMD", Case Code (Imperial)=0805, Case Code (Metric)=2012, Color=Yellow, Forward Current=30mA, Forward Voltage=2V, Lens Color=Colorless, Manufacturer=LITE-ON, Max Operating Temperature=85°C, Max Power Dissipation=75mW, Min Operating Temperature=-55°C, Package Quantity=1, Reverse Voltage=5V, Supplier Part Number 1=6920950, Test Current=20mA
D3 D4 D5 D6 D7: library part CMP-22017-000007-1, "LED GREEN CLEAR CHIP SMD", Case Code (Imperial)=0805, Case Code (Metric)=2012, Color=GREEN, Forward Current=30mA, Forward Voltage=2.1V, Illumination Color=Green, Lens Color=Colorless, Manufacturer=LITE-ON, Max Operating Temperature=85°C, Min Operating Temperature=-55°C, Package Quantity=1, Power Dissipation=100mW, Reverse Voltage=5V, Test Current=10mA
D8 D9 D10: "DIODE ARRAY SCHOTTKY 40V SOT363", Manufacturer="MICRO COMMERCIAL", Manufacturer Print=MICRO, Manufacturer_Name="Micro Commercial Components (MCC)", Package=SOT-363
D11 D13 D14: "LED PURPLE CLEAR 1206 SMD", Color=PURPLE, Manufacturer=Kingbright, Manufacturer Print=KINGBRIGHT, Package=1206, Supplier Part Number 1=604-APTR3216-VFX
D12: "LED PURPLE CLEAR 1206 SMD", Color=PURPLE, Manufacturer=KINGBRIGHT, Package=1206, Supplier Part Number 1=604-APTR3216-VFX
D15 D16: "DIODE SCHOTTKY 60V 2A SOD123FL", Average Rectified Current=2A, Forward Voltage=700mV, Manufacturer="MICRO COMMERCIAL", Max Operating Temperature=125°C, Max Power Dissipation=1.68W, Max Repetitive Reverse Voltage (Vrrm)=60V, Max Reverse Current=500uA, Max Surge Current=50A, Min Operating Temperature=-65°C, Package=SOD-123F, Package Quantity=1, Supplier Part Number 1=SMD26PL-TPMSCT-ND
D17 D18: "DIODE SCHOTTKY 60V 10A CFP15B", Case/Package=TO-277, Manufacturer=NEXPERIA
HS1: library part "LA 6 150 12", "HEATSINK EXTRUSION 150MM", Manufacturer="FISCHER ELEKTRONIK", Natural Thermal Resistance=0.175°C/W, Package=N/A, Power Consumption=2.9W, Supplier Part Number 1=42M1958
J1: "TERM BLOCK HDR 6POS VERT 5.08MM", Color=Green,Grey, Current=12A, Flammability Rating="UL94 V-0", Housing Color=Green, Manufacturer="PHOENIX CONTACT", Package=N/A, Package Quantity=50, Supplier Part Number 1=1896240, Voltage=300V, Voltage Rating=250V
J2 J3 J17 J18 J19: "TERM REDCUBE M4 8PIN PCB", Current Rating=80A, Manufacturer="WURTH ELEKTRONIK", Manufacturer Print=WURTH, Max Operating Temperature=135°C, Min Operating Temperature=-40°C, Package=N/A, Package Quantity=250, Supplier Part Number 1=1224952
J4: "CONN D-SUB PLUG 9POS R/A SLDR", Color=Black, Current Rating=5A, Manufacturer=AMPHENOL, Max Operating Temperature=155°C, Max Supply Voltage (AC)=250V, Min Operating Temperature=-55°C, Package=N/A, Supplier Part Number 1=70145033
J5 J6 J7 J12 J13 J14: "CONN MMCX JACK STR 50 OHM PCB", Manufacturer=MOLEX, Manufacturer Part Number=73415-1471, Max Frequency=6GHz, Operating Frequency=N/A, Package Quantity=500, Supplier Part Number 1=70364031
J8: "CONN HEADER VERT 12POS 2.54MM", Color=Black, Flammability Rating="UL94 V-0", Manufacturer="WURTH ELEKTRONIK", Manufacturer Print=WURTH, Max Operating Temperature=105°C, Min Operating Temperature=-40°C, Package=N/A, Supplier Part Number 1=732-5297-ND, Voltage Rating=250V
J9 J10: library part CMP-2000-05417-1, "CONN HEADER VERT 2POS 2.54MM", Color=White, Current, Rating="5 /  / A", Flammability Rating=UL94V-0, Manufacturer=TE, Package=N/A, Temperature, Operating="-55to+105 /  / degC", Voltage, Rating="250 /  / V"
J11 J15: "TERM BLOCK HDR 2POS VERT 5.08MM", Colour=Green, Manufacturer="PHOENIX CONTACT", Package=N/A, Supplier Part Number 1=1896199
J16: library part CMP-1502-00000-1, "CONN HEADER VERT 6POS 2.54MM", Contact Resistance=20mOhm, Manufacturer="WURTH ELECTRONIK", Operating Temperature=-40to125degC, Package=N/A, Withstanding Voltage=500VAC, Working Voltage=250VAC
J20: "CONN PWR JACK 2X5.5MM SOLDER", Color=Black, Current Rating=5A, Flammability Rating="UL94 V-0", Insulation Resistance=50MR, Manufacturer="CUI DEVICES", Max Operating Temperature=85°C, Min Operating Temperature=-25°C, Package=N/A, Package Quantity=280, Voltage Rating=24V
L1 L2 L3 L4 L5 L6: "CMC 10UH 1.6A 2LN 920 OHM SMD", Case/Package=SMD/SMT, Current=1.6A, DC Resistance (DCR)=80mR, Inductance=10uH, Manufacturer="WURTH ELECTRONIK", Manufacturer Print=WURTH, Max Operating Temperature=125°C, Min Operating Temperature=-40°C, Package=4-PC, Package Quantity=1, Supplier Part Number 1=9040408, Test Frequency=1kHz, Tolerance=30%, Voltage Rating=80V
L7: "FIXED IND 10UH 5.8A 20 MOHM SMD", Case/Package=N/A, Manufacturer="WURTH ELECTRONIK"
L8 L9: "FIXED IND 22UH 3.5A 74 MOHM SMD", Ambient Temperature Range High=85°C, Ambient Temperature Range Low=-40°C, DC Resistance (DCR)=64mΩ, Inductance=22µH, Inductance Tolerance=20%, Manufacturer="WURTH ELECTRONIK", Max Operating Temperature=125°C, Package=N/A, RMS Current (Irms)=3.5A, Saturation Current=5A, Self Resonant Frequency=7MHz, Series Resistance=74mΩ, Test Frequency=100kHz
MH1 MH2 MH3 MH4: "HEX STANDOFF M4 ALUMINUM 51MM F-F", Manufacturer=MCMASTER-CARR, Manufacturer Part Number=95947A552, Package=N/A
Q1: library part CMP-1048-00731-1, "TRANS NPN 45V 0.5A SOT23-3", Manufacturer=ONSEMI, Package=SOT-23-3
Q2: library part CCB021M12FM3, "SIC 6N-CH 1200V 30A MODULE", Manufacturer=WOLFSPEED, Mfr_Name="Cree Wolfspeed", Package=FMC
Q3 Q4: library part CMP-1046-00010-1, "TRANS NPN 80V 8A DPAK", Manufacturer=ONSEMI, Package=TO-252-3
Q5 Q6: "MOSFET N-CH 120V 90A PWRDI5060-8", Manufacturer="DIODES INC", Package=8-PowerTDFN, Supplier Part Number 1=68AH9585
R1 R2 R3 R4 R5 R6 R7 R8 R9 R10 R11 R12: library part CMP-03211-002966-1, "RES 220K OHM 1% 2W 2512", Ambient Temperature Range High=+70°C, Manufacturer=TE, Package=2512, Power Rating=2W, Resistance=220kΩ, Temperature="-55°C to +155°C", Temperature Coefficient=±100ppm/°C, Temperature Range High=+155°C, Temperature Range Low=-55°C, Tolerance=0.01, Voltage Rating=500V
R13 R14 R15 R16 R17 R18 R19 R20 R21 R22 R23 R24 R25 R26 R27 R28 R29 R30 R31 R32 R33 R34 R35 R36 R149 R150 R151 R152 R153 R154 R155 R156 R157 R158 R159 R160 R161 R162 R163 R164 R165 R166 R167 R168 R169 R170 R171 R172: library part CMP-2003-04604-1, "RES 249K OHM 0.1% 1/4W 1206", Manufacturer="VISHAY DALE", Package=1206, Power=0.25W, Resistance=249kΩ
R37 R39 R41 R43 R174 R176 R178 R180: "RES 4.99K OHM 1% 1/10W 0603", Case Code (Imperial)=0603, Case Code (Metric)=1608, Manufacturer=YAGEO, Max Operating Temperature=155°C, Max Power Dissipation=0.1W, Min Operating Temperature=-55°C, Package Quantity=1, Resistance=4.99kΩ, Resistance Tolerance=1%, Resistor Type="Thick Film", Supplier Part Number 1=1995595, Temperature Coefficient=100ppm/°C, Voltage Rating=75V, Voltage Rating (DC)=50V
R38 R179: "RES SMD 3.74K OHM 0.1% 1/5W 0603", Case Code (Imperial)=0603, Case Code (Metric)=1608, Manufacturer=PANASONIC, Max Operating Temperature=155°C, Max Power Dissipation=0.2W, Min Operating Temperature=-55°C, Resistance=3.74kΩ, Resistor Type="Thick Film", Temperature Coefficient=50ppm/°C, Tolerance=0.1%
R40 R42 R44 R173 R175 R177: "RES SMD 1.8K OHM 0.1% 1/5W 0603", Case Code (Imperial)=0603, Case Code (Metric)=1608, Manufacturer=PANASONIC, Max Operating Temperature=155°C, Max Power Dissipation=0.2W, Min Operating Temperature=-55°C, Resistance=1.8kΩ, Resistor Type="Thick Film", Temperature Coefficient=50ppm/°C, Tolerance=0.1%
R45 R50 R55 R57 R64 R71 R72 R75 R76 R81 R84 R85 R86 R87 R90 R94 R95 R96 R98 R99 R100 R103 R104 R118 R119 R121 R122 R189 R192: "RES SMD 49.9 OHM 1% 1/10W 0603", Case Code (Imperial)=0603, Case Code (Metric)=1608, Manufacturer=PANASONIC, Max Operating Temperature=155°C, Max Power Dissipation=100mW, Min Operating Temperature=-55°C, Package Quantity=5000, Power Rating=0.1W, Resistance=49.9Ω, Resistance Tolerance=1%, Resistor Type="Thick Film", Supplier Part Number 1=12AC1058, Temperature Coefficient=100ppm/°C, Voltage Rating=75V, Voltage Rating (DC)=50V, Working Voltage=6V
R46 R52 R54 R59 R61 R67 R68 R83 R88 R89 R91 R112 R113 R127 R130 R131 R133 R203 R222 R229 R232 R237 R241 R243: "RES SMD 10K OHM 1% 1/10W 0603", Case Code (Imperial)=0603, Case Code (Metric)=1608, Manufacturer=PANASONIC, Manufacturer Part Number=ERJ-3EKF1002V, Max Operating Temperature=155°C, Max Power Dissipation=0.1W, Min Operating Temperature=-55°C, Package Quantity=1, Power Rating=100mW, Resistance=10kΩ, Resistance Tolerance=1%, Resistor Type="Thick Film", Supplier Part Number 1=1051156, Temperature Coefficient=100ppm/°C, Voltage Rating=75V
R47 R128 R140 R145: "RES SMD 20K OHM 1% 1/10W 0603", Case Code (Imperial)=0603, Case Code (Metric)=1608, Manufacturer="VISHAY DALE", Max Operating Temperature=155°C, Max Power Dissipation=100mW, Min Operating Temperature=-55°C, Package Quantity=5000, Power Rating=0.1W, Resistance=20kΩ, Resistance Tolerance=1%, Resistor Type="Thick Film", Temperature Coefficient=100ppm/°C, Voltage Rating=75V
R48 R82 R97: "RES SMD 1.3K OHM 0.1% 1/10W 0603", Case Code (Imperial)=0603, Case Code (Metric)=1608, Manufacturer=PANASONIC, Manufacturer Part Number=ERA-3AEB132V, Max Operating Temperature=155°C, Max Power Dissipation=100mW, Min Operating Temperature=-55°C, Package Quantity=1, Power Rating=0.1W, Ratings=AEC-Q200, Resistance=1.3kΩ, Resistance Tolerance=0.1%, Resistor Type="Thin Film", Temperature Coefficient=25ppm/°C, Voltage Rating=75V
R49: "RES SMD 15.4K OHM 1% 1/10W 0603", Case Code (Imperial)=0603, Case Code (Metric)=1608, Manufacturer=SAMSUNG, Max Operating Temperature=155°C, Max Power Dissipation=100mW, Min Operating Temperature=-55°C, Package Quantity=1, Power Rating=0.1W, Resistance=15.4kΩ, Resistor Type="Thick Film", Temperature Coefficient=100ppm/°C, Tolerance=1%, Voltage Rating (DC)=50V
